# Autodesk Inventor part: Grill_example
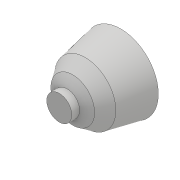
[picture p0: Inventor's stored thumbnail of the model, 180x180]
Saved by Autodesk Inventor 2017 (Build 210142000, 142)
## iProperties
Created: 2016-08
Part Number: Grill_example
Material: Generic
Document SubType Name: Modeling
Designer: Gaurav
Density: 1 g/cm^3
Appearance: Default
Author: Gaurav
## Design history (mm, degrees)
sketch "Sketch2"
  geometry: L1 (-259.283, 423.583)-(-211.104, 178.832); L2 (-211.104, 178.832)-(-150.941, 92.632); L3 (-150.941, 92.632)-(-86.288, 54.045); L4 (-86.288, 54.045)-(-86.288, 0); L5 (-86.288, 0)-(0, 0); L6 (-259.283, 423.583)-(0, 423.583); L7 (0, 423.583)-(0, 0)
  constraints: 14 end point, 2 perpendicular, 1 horizontal, 1 point on line, 1 vertical
revolve "Revolution1" sketch "Sketch2" stored, may be unused: angle "d3" = 90 deg
shell "Shell1" dims "d4" = 3
sketch "Sketch3"
  geometry: L1 (370, 152)-(370, -166); L2 (370, -166)-(244, -166); L3 (244, -166)-(244, 152); L4 (244, 152)-(370, 152); L5 (370, 119)-(244, 119); L6 (370, 83.288)-(244, 83.288); L7 (370, 43)-(244, 43); L8 (370, -54)-(244, -54); L9 (370, -110)-(244, -110); L10 (275, 152)-(275, -166); L11 (335, 152)-(335, -166); L12 (352, -76)-(262, -76); L13 (262, -76)-(262, 62); L14 (262, 62)-(352, 62); L15 (352, 62)-(352, -76); L16 (352, -76)-(262, 62); L17 (262, -76)-(352, 62); 2 further points
  constraints: 34 end point, 14 point on line, 10 perpendicular, 3 parallel, 2 midpoint, 1 horizontal, 1 vertical
feature "Grill4" dims "d51" = 3, "d52" = 0, "d53" = 2, "d54" = 3, "d55" = 0, "d56" = 2, "d57" = 0, "d58" = 0, "d59" = 2, "d60" = 3, "d61" = 0, "d62" = 0, "d63" = 3029.97523
body "Solid2"
other parameters: "d49" = 2, "d50" = 2
